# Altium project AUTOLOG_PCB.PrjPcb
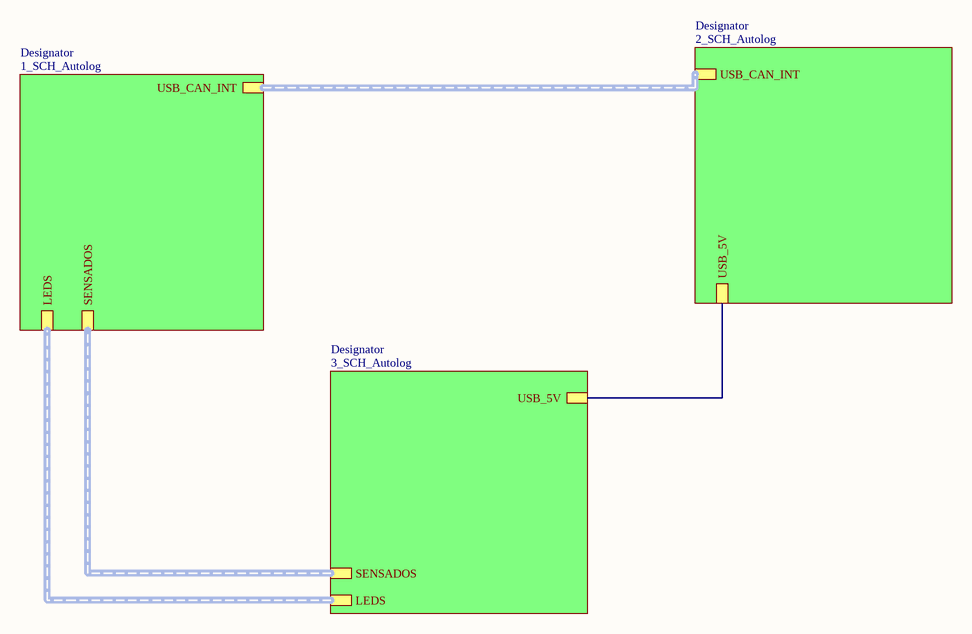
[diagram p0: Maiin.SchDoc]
4 sheets, 80 parts. Net scope: hierarchical (ports join the sheet entries above them; power ports are global).
Board file: PCB_Autolog.PcbDoc
Sheets:
  Maiin.SchDoc
    Designator = 1_SCH_Autolog.SchDoc
    Designator = 2_SCH_Autolog.SchDoc
    Designator = 3_SCH_Autolog.SchDoc

## Sheet Maiin.SchDoc: PROYECTO FINAL - AutoLog
size A4; Author: Nathalia Mora; Revision: V1R1; SheetNumber: 1; SheetTotal: 4; Name:: Marlyn Nathalia Mora Riascos

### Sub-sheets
Designator = 1_SCH_Autolog: LEDS (harness LEDS_HARNEERS), SENSADOS (harness SENSADO HARNEERS), USB_CAN_INT (harness USB_CAN_INT_HARNEERS)
Designator = 2_SCH_Autolog: USB_5V, USB_CAN_INT (harness USB_CAN_INT_HARNEERS)
Designator = 3_SCH_Autolog: LEDS (harness LEDS_HARNEERS), SENSADOS (harness SENSADO HARNEERS), USB_5V

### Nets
VBUSS: sheet Designator/USB_5V, sheet Designator/USB_5V

## Sheet 1_SCH_Autolog.SchDoc: PROYECTO FINAL - AutoLog
size A4; Revision: V1R1; SheetNumber: 2; SheetTotal: 4
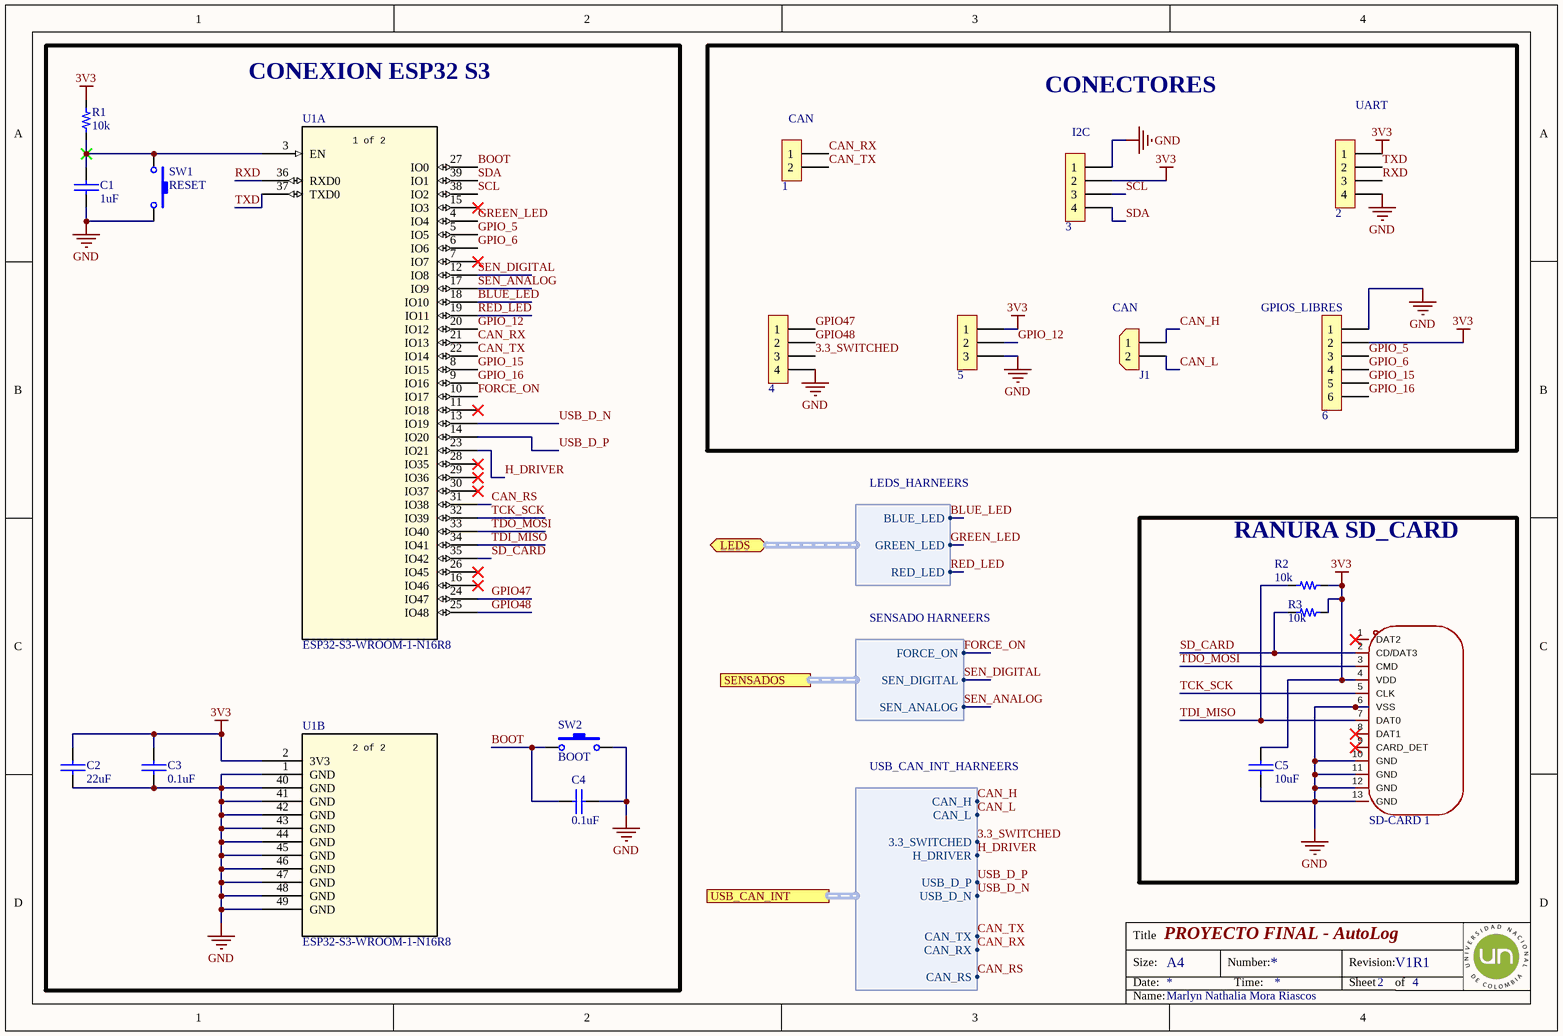
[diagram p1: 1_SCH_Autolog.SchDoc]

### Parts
1  2x1  [H_2x1_TH_100mil]  (value not drawn)  (no BOM)
2  4x1  [H_4x1_TH_2.54mm]  (value not drawn)  (no BOM)
3  4x1  [H_4x1_TH_2.54mm]  (value not drawn)  (no BOM)
4  4x1  [H_4x1_TH_2.54mm]  (value not drawn)  (no BOM)
5  3x1  [H_3X1_TH_100mil]  (value not drawn)  (no BOM)
6  6x1  [H_6x1_TH_100mil]  (value not drawn)  (no BOM)
C1  value 1uF  [0603_cap]  (hidden comment: 1uF 50V)
C2  value 22uF  [0805_cap]  (hidden comment: 22uF 16V)
C3  value 0.1uF  [0603_cap]  (hidden comment: 0.1uF 50V)
C4  value 0.1uF  [0603_cap]  (hidden comment: 0.1uF 50V)
C5  value 10uF  [0603_cap]  (hidden comment: 10uF 10V)
J1  CAN  [CON_2x1_TH_5MM]
R1  value 10k  [0603_res]  (hidden comment: 10k 1/10W)
R2  value 10k  [0603_res]  (hidden comment: 10k 1/10W)
R3  value 10k  [0603_res]  (hidden comment: 10k 1/10W)
SD-CARD_1  Micro_SD_socket  [MICROSD CARD SMD]  (value not drawn)
SW1  RESET  [Sw_PUSH_4.5x4.5x5mm]
SW2  BOOT  [Sw_PUSH_4.5x4.5x5mm]
U1  ESP32-S3-WROOM-1-N16R8  [ESP32S3WROOM1N8R2]  (parts A,B of 2)

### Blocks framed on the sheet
CONEXION ESP32 S3: C1-C4 R1 SW1 SW2 U1
CONECTORES: 1-6 J1
RANURA SD_CARD: C5 R2 R3 SD-CARD_1

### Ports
LEDS (bidir, harness LEDS_HARNEERS, see Maiin[2B], 3_SCH_Autolog[4C]), SENSADOS (harness SENSADO HARNEERS, see Maiin[2B], 3_SCH_Autolog[3A]), USB_CAN_INT (harness USB_CAN_INT_HARNEERS, see Maiin[2A], 2_SCH_Autolog[1D])

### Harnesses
LEDS_HARNEERS: RED_LED, GREEN_LED, BLUE_LED
SENSADO HARNEERS: FORCE_ON, SEN_DIGITAL, SEN_ANALOG
USB_CAN_INT_HARNEERS: USB_D_P, USB_D_N, H_DRIVER, 3.3_SWITCHED, CAN_L, CAN_TX, CAN_RX, CAN_RS, CAN_H

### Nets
3V3: 2.1 3.2 5.1 6.2 C2.1 C3.1 C5.2 R1.2 R2.2 R3.2 SD-CARD_1.4(VDD) U1.2(3V3)
GND: 2.4 3.1 4.4 5.3 6.1 C1.2 C2.2 C3.2 C4.1 C5.1 SD-CARD_1.6(VSS) SD-CARD_1.10(GND) SD-CARD_1.11(GND) SD-CARD_1.12(GND) SD-CARD_1.13(GND) SW1.2 SW2.2 U1.1(GND) U1.40(GND) U1.41(GND) U1.42(GND) U1.43(GND) U1.44(GND) U1.45(GND) U1.46(GND) U1.47(GND) U1.48(GND) U1.49(GND)
3.3_SWITCHED: 4.3 ; port USB_CAN_INT.3.3_SWITCHED
BLUE_LED: U1.18(IO10) ; port LEDS.BLUE_LED
BOOT: C4.2 SW2.1 U1.27(IO0)
CAN_H: J1.1 ; port USB_CAN_INT.CAN_H
CAN_L: J1.2 ; port USB_CAN_INT.CAN_L
CAN_RS: U1.31(IO38) ; port USB_CAN_INT.CAN_RS
CAN_RX: 1.1 U1.21(IO13) ; port USB_CAN_INT.CAN_RX
CAN_TX: 1.2 U1.22(IO14) ; port USB_CAN_INT.CAN_TX
FORCE_ON: U1.10(IO17) ; port SENSADOS.FORCE_ON
GPIO47: 4.1 U1.24(IO47)
GPIO48: 4.2 U1.25(IO48)
GPIO_5: 6.3 U1.5(IO5)
GPIO_6: 6.4 U1.6(IO6)
GPIO_12: 5.2 U1.20(IO12)
GPIO_15: 6.5 U1.8(IO15)
GPIO_16: 6.6 U1.9(IO16)
GREEN_LED: U1.4(IO4) ; port LEDS.GREEN_LED
H_DRIVER: U1.23(IO21) ; port USB_CAN_INT.H_DRIVER
RED_LED: U1.19(IO11) ; port LEDS.RED_LED
RXD: 2.3 U1.36(RXD0)
SCL: 3.3 U1.38(IO2)
SD_CARD: R3.1 SD-CARD_1.2(CD/DAT3) U1.35(IO42)
SDA: 3.4 U1.39(IO1)
SEN_ANALOG: U1.17(IO9) ; port SENSADOS.SEN_ANALOG
SEN_DIGITAL: U1.12(IO8) ; port SENSADOS.SEN_DIGITAL
TCK_SCK: SD-CARD_1.5(CLK) U1.32(IO39)
TDI_MISO: R2.1 SD-CARD_1.7(DAT0) U1.34(IO41)
TDO_MOSI: SD-CARD_1.3(CMD) U1.33(IO40)
TXD: 2.2 U1.37(TXD0)
USB_D_N: U1.13(IO19) ; port USB_CAN_INT.USB_D_N
USB_D_P: U1.14(IO20) ; port USB_CAN_INT.USB_D_P
NetC1_1: C1.1 R1.1 SW1.1 U1.3(EN)

Not connected (* = marked no-connect by the designer): SD-CARD_1 1(DAT2)* 8(DAT1)* 9(CARD_DET)*; U1 7(IO7)* 11(IO18)* 15(IO3)* 16(IO46)* 26(IO45)* 28(IO35)* 29(IO36)* 30(IO37)*

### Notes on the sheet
- (near 2) UART
- (near 1) CAN
- (near 3) I2C
- (near 6) GPIOS_LIBRES

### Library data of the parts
1 = H_Male_2x1_TH_100mil
2-4 = H_Male_4x1_TH_100mil
5 = H_Male_3x1_TH_100mil
6 = H_Male_6x1_TH_100mil
C1 = Cap_1uF_0603_50V: 50V 1uF X5R ±10% 0603 Multilayer Ceramic Capacitors MLCC - SMD/SMT ROHS; Manufacturer: Samsung Electro-Mechanics; Manufacturer Part Number: CL10A105KB8NNNC
C2 = Cap_22uF_0805_16V: 16V 22uF X5R ±20% 0805 Multilayer Ceramic Capacitors MLCC - SMD/SMT ROHS; Manufacturer: Chinocera; Manufacturer Part Number: HGC0805R5226M160NSLJ
C3 C4 = Cap_0.1uF_0603_50V: 50V 100nF Y5V -20%~+80% 0603 Multilayer Ceramic Capacitors MLCC - SMD/SMT ROHS; Manufacturer: Walsin Tech Corp; Manufacturer Part Number: 0603F104Z500CT
C5 = Cap_10uF_0603_10V: 10V 10uF X5R ±10% 0603 Multilayer Ceramic Capacitors MLCC - SMD/SMT ROHS; Manufacturer: CCTC; Manufacturer Part Number: TCC0603X5R106K100CT
J1 = Con_2x1_TH_5mm: 2POS 5MM; Manufacturer: JILN; Manufacturer Part Number: JL126-50002G01
R1-R3 = Res_10k_0603_1/10W: RES SMD 10k OHM 5% 1/10W 0603; Manufacturer: FOJAN; Manufacturer Part Number: FRC0603J103TS
SD-CARD_1 = Micro_SD_socket: CONN MICROSD CARD R/A SMD; Manufacturer: ATOM; Manufacturer Part Number: MR01A-01211
SW1 SW2 = Sw_PUSH_4.5x4.5x5.0xmm: SWITCH TACTILE SPST-NO 0.05A 12V; Manufacturer: BZCN; Manufacturer Part Number: TSC015A05026A
U1 = ESP32-S3-WROOM-1-N16R8  nnnnn: ESP32-S3 Wi-Fi & Bluetooth 5 MCU module, 16MB Flash, 8MB PSRAM.; Manufacturer: Espressif Systems; Suplier  Part Number: 5407-ESP32-S3-WROOM-1-N16R8TR-ND

## Sheet 2_SCH_Autolog.SchDoc: PROYECTO FINAL - AutoLog
size A4; SheetNumber: 3; SheetTotal: 4
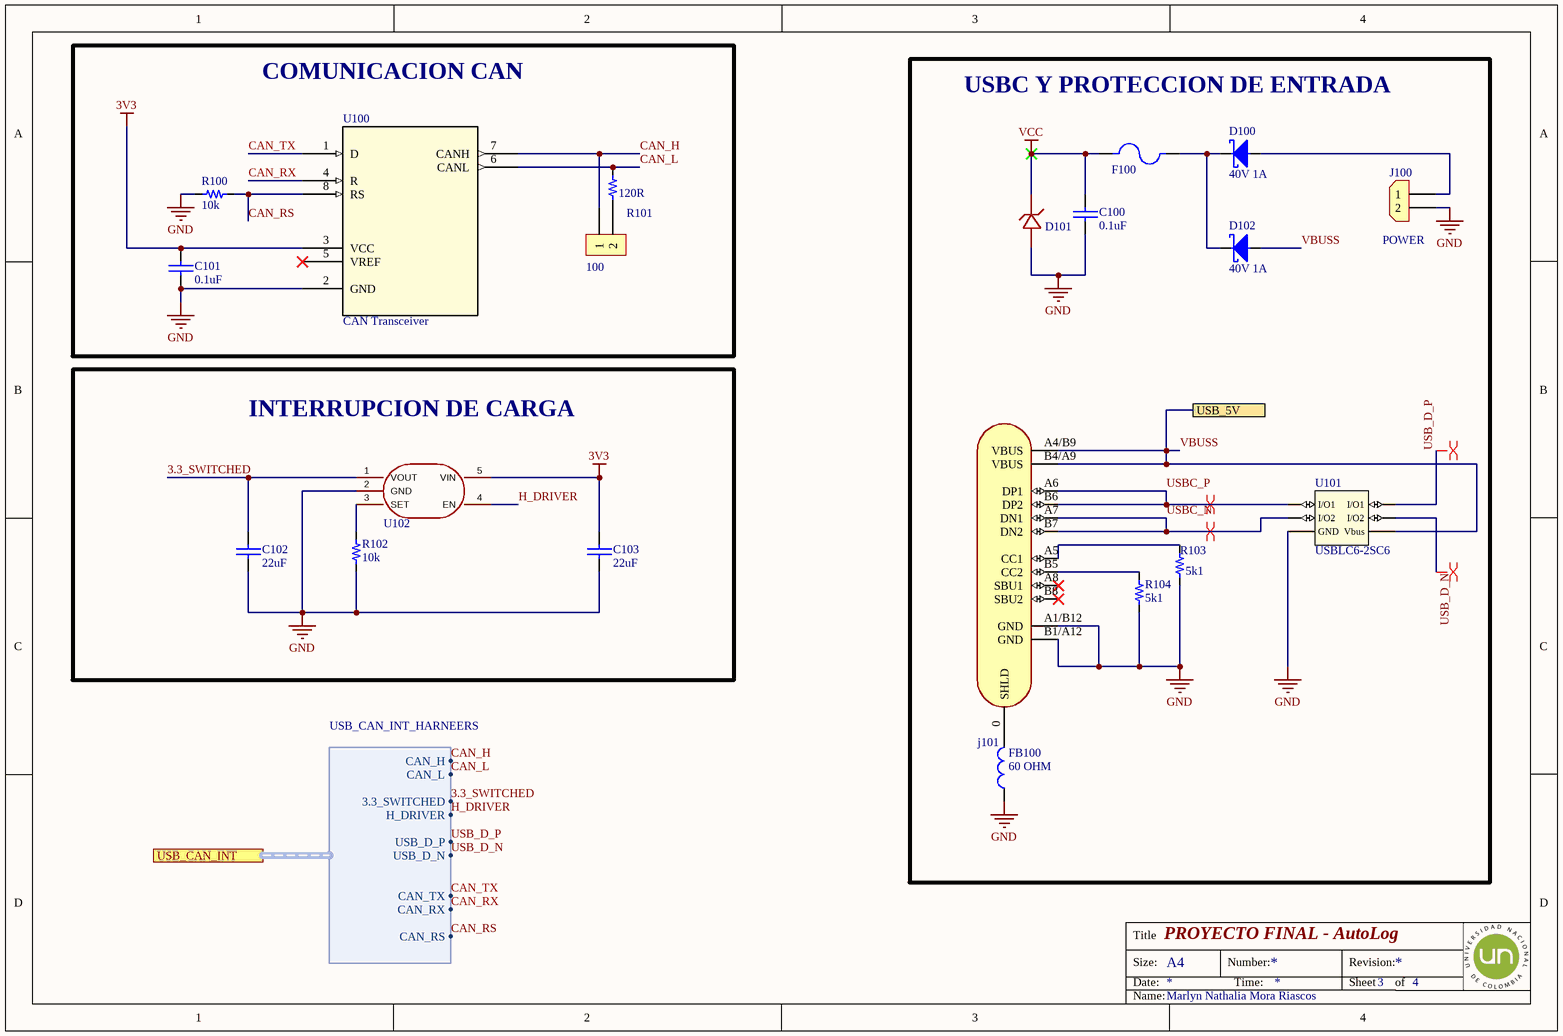
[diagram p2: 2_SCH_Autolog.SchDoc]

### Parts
100  2x1  [H_2x1_TH_100mil]  (value not drawn)  (no BOM)
C100  value 0.1uF  [0603_cap]  (hidden comment: 0.1uF 50V)
C101  value 0.1uF  [0603_cap]  (hidden comment: 0.1uF 50V)
C102  value 22uF  [0603_cap]  (hidden comment: 22uF 10V)
C103  value 22uF  [0603_cap]  (hidden comment: 22uF 10V)
D100  40V 1A  [SOD_123]
D101  TVS_DIODE_SMF30A  [TVS_DIODE_SMF30A]  (value not drawn)
D102  40V 1A  [SOD_123]
F100  PTC_MF-MSMF110/16-2  [FUSER_MF-MSMF110/16-2]  (value not drawn)
FB100  value 60 OHM  [0603_fb]  (hidden comment: 60OHM 2A)
J100  POWER  [CON_2x1_TH_5MM]
j101  USB C  [CON_USB_C_16P_RA]  (value not drawn)
R100  value 10k  [0603_res]  (hidden comment: 10k 1/10W)
R101  value 120R  [0603_res]  (hidden comment: 120R 1/10W)
R102  value 10k  [0603_res]  (hidden comment: 10k 1/10W)
R103  value 5k1  [0603_res]  (hidden comment: 5k1 1/10W)
R104  value 5k1  [0603_res]  (hidden comment: 5k1 1/10W)
U100  CAN Transceiver  [D8-M]
U101  USBLC6-2SC6  [SOT_23_6]
U102  MT9700  [SOT-23-5_L3.0-W1.7-P0.95-LS2.8-BR]  (value not drawn)

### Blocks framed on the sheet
COMUNICACION CAN: 100 C101 R100 R101 U100
USBC Y PROTECCION DE ENTRADA: C100 D100-D102 F100 FB100 J100 j101 R103 R104 U101
INTERRUPCION DE CARGA: C102 C103 R102 U102

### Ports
USB_5V (see Maiin[3B], 3_SCH_Autolog[3A]), USB_CAN_INT (harness USB_CAN_INT_HARNEERS, see Maiin[3A], 1_SCH_Autolog[2D])

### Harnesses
USB_CAN_INT_HARNEERS: USB_D_P, USB_D_N, H_DRIVER, 3.3_SWITCHED, CAN_L, CAN_TX, CAN_RX, CAN_RS, CAN_H

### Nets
3V3: C101.2 C103.1 U100.3(VCC) U102.5(VIN)
GND: C100.1 C101.1 C102.2 C103.2 D101.2 FB100.1 J100.2 j101.A1/B12(GND) j101.B1/A12(GND) R100.1 R102.1 R103.1 R104.2 U100.2(GND) U101.2(GND) U102.2(GND)
VCC: C100.2 D101.1 F100.1
3.3_SWITCHED: C102.1 U102.1(VOUT) ; port USB_CAN_INT.3.3_SWITCHED
CAN_H: 100.1 U100.7(CANH) ; port USB_CAN_INT.CAN_H
CAN_L: R101.2 U100.6(CANL) ; port USB_CAN_INT.CAN_L
CAN_RS: R100.2 U100.8(RS) ; port USB_CAN_INT.CAN_RS
CAN_RX: U100.4(R) ; port USB_CAN_INT.CAN_RX
CAN_TX: U100.1(D) ; port USB_CAN_INT.CAN_TX
H_DRIVER: U102.4(EN) ; port USB_CAN_INT.H_DRIVER
USB_D_N: U101.4(I/O2) ; port USB_CAN_INT.USB_D_N
USB_D_P: U101.6(I/O1) ; port USB_CAN_INT.USB_D_P
USBC_N: j101.A7(DN1) j101.B7(DN2) U101.3(I/O2)
USBC_P: j101.A6(DP1) j101.B6(DP2) U101.1(I/O1)
VBUSS: D102.2 j101.A4/B9(VBUS) j101.B4/A9(VBUS) U101.5(Vbus) ; port USB_5V
Net100_2: 100.2 R101.1
NetD100_1: D100.1 D102.1 F100.2
NetD100_2: D100.2 J100.1
NetFB100_2: FB100.2 j101.0(SHLD)
Netj101_A5: j101.A5(CC1) R103.2
Netj101_B5: j101.B5(CC2) R104.1
NetR102_2: R102.2 U102.3(SET)

Not connected (* = marked no-connect by the designer): j101 A8(SBU1)* B8(SBU2)*; U100 5(VREF)*

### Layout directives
differential pair: USB_D_N, USB_D_P, USBC_N, USBC_P

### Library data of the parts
100 = H_Male_2x1_TH_100mil
C100 C101 = Cap_0.1uF_0603_50V: as C3 on sheet 1_SCH_Autolog
C102 C103 = Cap_22uF_0603_10V: 10V 22uF X5R ±20% 0603 Multilayer Ceramic Capacitors MLCC - SMD/SMT ROHS; Manufacturer: HRE; Manufacturer Part Number: CGA0603X5R226M100JT
D100 D102 = D_Schottky_40V_1A_SOD_123F: DIODE SCHOTTKY 40V 1A SOD123F; Manufacturer: Shanghai Prisemi Elec; Manufacturer Part Number: PSBD1DF40V1H
D101 = TVS_DIODE_SMF30A: TVS DIODE 30VWM 48.4VC SOD123F; Manufacturer: Diotec Semiconductor; Manufacturer Part Number: SMF30A
F100 = PTC_MF-MSMF110/16-2: Polymeric PTC Resettable Fuse 16V 1.1 A Ih Surface Mount 1812 (4532 Metric), Concave; Manufacturer: Bourns Inc.
FB100 = FB_60_0603_2A: 2A 1 100mΩ 60Ω@100MHz ±25% 0603 Ferrite Beads ROHS; Manufacturer: TAI-TECH; Manufacturer Part Number: HCB1608KF-600T20
J100 = Con_2x1_TH_5mm: as J1 on sheet 1_SCH_Autolog
j101 = CON_USB_TYPEC_16P: 3A USB 3.1 1 Surface Mount 16P Female -40℃~+85℃ Type-C SMD USB Connectors ROHS; Manufacturer: SHOU HAN; Manufacturer Part Number: TYPE-C-3.1-16PIN
R100 R102 = Res_10k_0603_1/10W: as R1 on sheet 1_SCH_Autolog
R101 = Res_120R_0603_1/10W: 100mW Thick Film Resistor 75V ±100ppm/℃ ±1% 120Ω 0603 Chip Resistor - Surface Mount ROHS; Manufacturer: FOJAN; Manufacturer Part Number: FRC0603F1200TS
R103 R104 = Res_5k1_0603: RES 5.1kΩ ±1% 100mW 0603; Manufacturer: YAGEO; Manufacturer Part Number: RC0603FR-0773K2L
U100 = SN65HVD230DR-CAN: Transceiver Half CANbus 8-SOIC; Manufacturer: Texas Instruments; Suplier  Part Number: 296-11654-2-ND
U101 = TVS_5.25V_2CH_SOT_23_6: TVS DIODE 5.25V 17V SOT23-6; Manufacturer: STMicroelectronics
U102 = MT9700: Switch de potencia con límite de corriente y control enable para corte en sleep de periféricos y MicroSD; Manufacturer: XI'AN Aerosemi Tech

## Sheet 3_SCH_Autolog.SchDoc: PROYECTO FINAL - AutoLog
size A4; Revision: V1R1; SheetNumber: 4; SheetTotal: 4
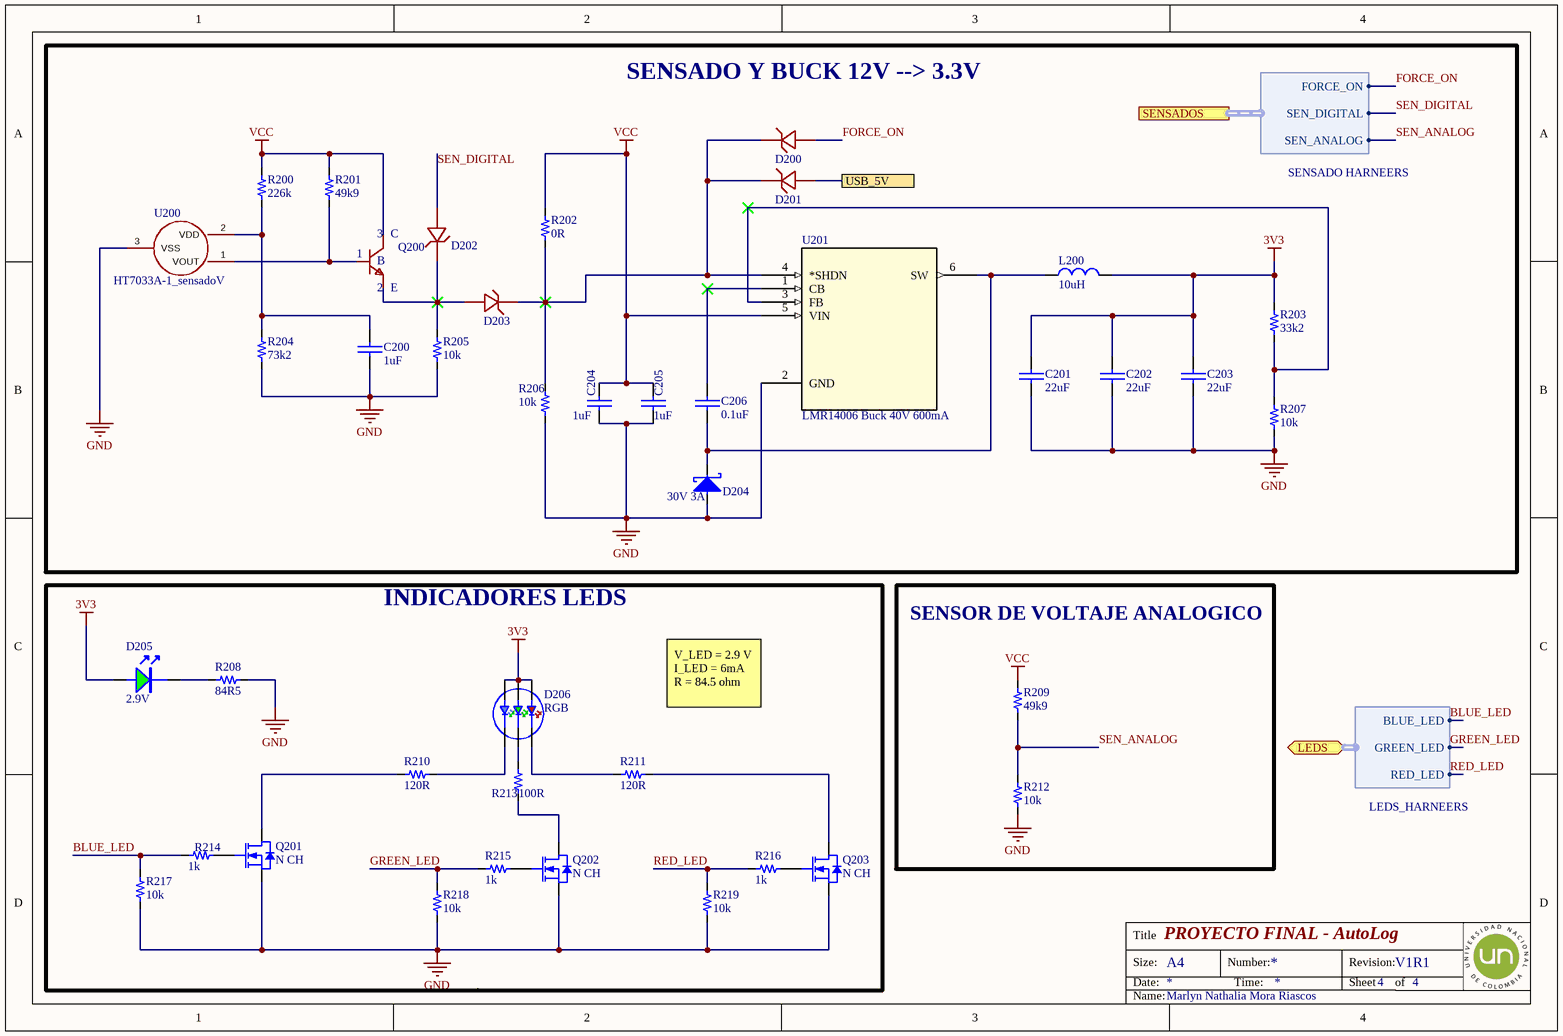
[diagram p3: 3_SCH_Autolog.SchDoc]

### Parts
C200  value 1uF  [0603_cap]  (hidden comment: 1uF 50V)
C201  value 22uF  [0603_cap]  (hidden comment: 22uF 10V)
C202  value 22uF  [0603_cap]  (hidden comment: 22uF 10V)
C203  value 22uF  [0603_cap]  (hidden comment: 22uF 10V)
C204  value 1uF  [0603_cap]  (hidden comment: 1uF 50V)
C205  value 1uF  [0603_cap]  (hidden comment: 1uF 50V)
C206  value 0.1uF  [0603_cap]  (hidden comment: 0.1uF 50V)
D200  1N4148WS  [SOD-323_1N4148]  (value not drawn)
D201  1N4148WS  [SOD-323_1N4148]  (value not drawn)
D202  1N4148WS  [SOD-323_1N4148]  (value not drawn)
D203  1N4148WS  [SOD-323_1N4148]  (value not drawn)
D204  30V 3A  [SMA]
D205  2.9V  [0805_LED]
D206  RGB  [RGB_NS_3.5X3.7]
L200  value 10uH  [Ind_5.8*5.2_NS]  (hidden comment: 10uH 1.42A)
Q200  SS8050  [SOT-23-3_TRANS NPN]  (value not drawn)
Q201  N CH  [SOT_23_3]
Q202  N CH  [SOT_23_3]
Q203  N CH  [SOT_23_3]
R200  value 226k  [0603_res]  (hidden comment: 226k 1/10W)
R201  value 49k9  [0603_res]  (hidden comment: 49k9 1/10W)
R202  value 0R  [0603_res]  (hidden comment: 0R 1/10W)
R203  value 33k2  [0603_res]  (hidden comment: 33k2 1/10W)
R204  value 73k2  [0603_res]  (hidden comment: 73k2 1/10W)
R205  value 10k  [0603_res]  (hidden comment: 10k 1/10W)
R206  value 10k  [0603_res]  (hidden comment: 10k 1/10W)
R207  value 10k  [0603_res]  (hidden comment: 10k 1/10W)
R208  value 84R5  [0603_res]  (hidden comment: 84R5 1/10W)
R209  value 49k9  [0603_res]  (hidden comment: 49k9 1/10W)
R210  value 120R  [0603_res]  (hidden comment: 120R 1/10W)
R211  value 120R  [0603_res]  (hidden comment: 120R 1/10W)
R212  value 10k  [0603_res]  (hidden comment: 10k 1/10W)
R213  value 100R  [0603_res]  (hidden comment: 100R 1/10W)
R214  value 1k  [0603_res]  (hidden comment: 1k 1/10W)
R215  value 1k  [0603_res]  (hidden comment: 1k 1/10W)
R216  value 1k  [0603_res]  (hidden comment: 1k 1/10W)
R217  value 10k  [0603_res]  (hidden comment: 10k 1/10W)
R218  value 10k  [0603_res]  (hidden comment: 10k 1/10W)
R219  value 10k  [0603_res]  (hidden comment: 10k 1/10W)
U200  HT7033A-1_sensadoV  [SOT-89-3_L4.5-W2.5-P1.50-LS4.2-BR]
U201  LMR14006 Buck 40V 600mA  [DDC6_TEX-M]

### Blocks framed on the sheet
SENSADO Y BUCK 12V --> 3.3V: C200-C206 D200-D204 L200 Q200 R200-R207 U200 U201
INDICADORES LEDS: D205 D206 Q201-Q203 R208 R210 R211 R213-R219
SENSOR DE VOLTAJE ANALOGICO: R209 R212

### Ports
LEDS (bidir, harness LEDS_HARNEERS, see Maiin[2C], 1_SCH_Autolog[2C]), SENSADOS (harness SENSADO HARNEERS, see Maiin[2C], 1_SCH_Autolog[2C]), USB_5V (see Maiin[3C], 2_SCH_Autolog[4B])

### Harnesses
LEDS_HARNEERS: RED_LED, GREEN_LED, BLUE_LED
SENSADO HARNEERS: FORCE_ON, SEN_DIGITAL, SEN_ANALOG

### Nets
3V3: C201.1 C202.1 C203.1 D205.1(A) D206.4 D206.5 D206.6 L200.2 R203.2
GND: C200.2 C201.2 C202.2 C203.2 C204.2 C205.2 D204.2 Q201.2(S) Q202.2(S) Q203.2(S) R204.1 R205.1 R206.1 R207.1 R208.2 R212.1 R217.2 R218.1 R219.1 U200.3(VSS) U201.2(GND)
VCC: C204.1 C205.1 Q200.3(C) R200.2 R201.1 R202.2 R209.2 U201.5(VIN)
BLUE_LED: R214.1 R217.1 ; port LEDS.BLUE_LED
FORCE_ON: D200.2 ; port SENSADOS.FORCE_ON
GREEN_LED: R215.1 R218.2 ; port LEDS.GREEN_LED
RED_LED: R216.1 R219.2 ; port LEDS.RED_LED
SEN_ANALOG: R209.1 R212.2 ; port SENSADOS.SEN_ANALOG
SEN_DIGITAL: D202.2 ; port SENSADOS.SEN_DIGITAL
VBUSS: D201.2 ; port USB_5V
NetC200_1: C200.1 R200.1 R204.2 U200.2(VDD)
NetC206_1: C206.1 U201.1(CB)
NetC206_2: C206.2 D204.1 L200.1 U201.6(SW)
NetD200_1: D200.1 D201.1 D203.1 R202.1 R206.2 U201.4(*SHDN)
NetD202_1: D202.1 D203.2 Q200.2(E) R205.2
NetD205_2: D205.2 R208.1
NetD206_1: D206.1 R210.1
NetD206_2: D206.2 R213.1
NetD206_3: D206.3 R211.1
NetQ200_1: Q200.1(B) R201.2 U200.1(VOUT)
NetQ201_1: Q201.1(G) R214.2
NetQ201_3: Q201.3(D) R210.2
NetQ202_1: Q202.1(G) R215.2
NetQ202_3: Q202.3(D) R213.2
NetQ203_1: Q203.1(G) R216.2
NetQ203_3: Q203.3(D) R211.2
NetR203_1: R203.1 R207.2 U201.3(FB)

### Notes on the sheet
- V_LED = 2.9 V
  I_LED = 6mA
  R = 84.5 ohm

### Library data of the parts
C200 C204 C205 = Cap_1uF_0603_50V: as C1 on sheet 1_SCH_Autolog
C201-C203 = Cap_22uF_0603_10V: as C102 on sheet 2_SCH_Autolog
C206 = Cap_0.1uF_0603_50V: as C3 on sheet 1_SCH_Autolog
D200-D203 = 1N4148WS_DIODE: DIODE GP 100V 150mA SOD-323; Manufacturer: JSCJ
D204 = D_Schottky_40V_3A_SMA: 40V Independent 3A 550mV@3A SMA Schottky Diodes ROHS; Manufacturer: TDSEMIC; Manufacturer Part Number: SS34-TD
D205 = LED_0805_Green: LED GREEN CLEAR 0805 SMD; Manufacturer: XINGLIGHT; Manufacturer Part Number: XL-2012UGC
D206 = LED_RGB_3535_SMD: -30℃~+85℃ RGB 110° 3535(mm) Light Emitting Diodes (LED) ROHS; Manufacturer: Foshan NationStar Optoelectronics; Manufacturer Part Number: RS-3535MWAM
L200 = Inductor_10uH_1.42A_5.8*5.2mm: 1.42A 10uH ±10% 87.9mΩ SMD,5.8x5.2mm Inductors (SMD) ROHS; Manufacturer: SHOU HAN; Manufacturer Part Number: CY54-10UH
Q200 = TRANS_NPN_SS8050_SOT23: SS8050 Transistor BJT NPN 40V 1.5A; Manufacturer: JSCJ; Manufacturer Part Number: SS8050(RANGE:200-350)
Q201-Q203 = Q_NFET_20V_3.2A_SOT23: MOSFET N-CH 20V SOT23; Manufacturer: Doeshare; Manufacturer Part Number: DN2302S
R200 = Res_226k_0603_1/10W: 100mW Thick Film Resistors 75V ±100ppm/℃ ±1% 226kΩ 0603 Chip Resistor - Surface Mount ROHS; Manufacturer: YAGEO; Manufacturer Part Number: RC0603FR-07226KL
R201 R209 = Res_49k9_0603_1/10W: 100mW Thick Film Resistor 75V ±100ppm/℃ ±1% 49.9kΩ 0603 Chip Resistor - Surface Mount ROHS; Manufacturer: YAGEO; Manufacturer Part Number: RC0603FR-0749K9L
R202 = Res_0R_0603_1/10W: RES SMD 0R OHM 5% 1/10W 0603; Manufacturer: FOJAN; Manufacturer Part Number: FRC0603P000 TS
R203 = Res_33k2_0603_1/10W: 100mW Thick Film Resistor 75V ±100ppm/℃ ±1% 33.2kΩ 0603 Chip Resistor - Surface Mount ROHS; Manufacturer: YAGEO; Manufacturer Part Number: RC0603FR-0733K2L
R204 = Res_73k2_0603_1/10W: 100mW Thick Film Resistor 75V ±100ppm/℃ ±1% 73.2kΩ 0603 Chip Resistor - Surface Mount ROHS; Manufacturer: YAGEO; Manufacturer Part Number: RC0603FR-0773K2L
R205-R207 R212 R217-R219 = Res_10k_0603_1/10W: as R1 on sheet 1_SCH_Autolog
R208 = Res_84R5_0603_1/10W: 100mW Thick Film Resistor 50V ±100ppm/℃ ±1% 84.5Ω 0603 Chip Resistor - Surface Mount ROHS; Manufacturer: LIZ Elec; Manufacturer Part Number: CR0603FA84R5G
R210 R211 = Res_120R_0603_1/10W: as R101 on sheet 2_SCH_Autolog
R213 = Res_100R_0603_1/10W: RES SMD 100R OHM 5% 1/10W 0603; Manufacturer: FOJAN; Manufacturer Part Number: FRC0603J101 TS
R214-R216 = Res_1k_0603_1/10W: RES SMD 1k OHM 5% 1/10W 0603; Manufacturer: FOJAN; Manufacturer Part Number: FRC0603J102 TS
U200 = HOLTEK HT7033A-1_sensadoV: Detector de tensión con umbral de 3.3V; Manufacturer: HOLTEK; Suplier  Part Number: C73715
U201 = LMR14006XDDCR: IC REG BUCK ADJ 600MA SOT23; Manufacturer: Texas Instruments; Suplier  Part Number: 296-44318-2-ND

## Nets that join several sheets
3V3: 1_SCH_Autolog (12 pins), 2_SCH_Autolog (C101.2 C103.1 U100.3 U102.5), 3_SCH_Autolog (9 pins)
GND: 1_SCH_Autolog (28 pins), 2_SCH_Autolog (16 pins), 3_SCH_Autolog (21 pins)
VCC: 2_SCH_Autolog (C100.2 D101.1 F100.1), 3_SCH_Autolog (8 pins)
3.3_SWITCHED: 1_SCH_Autolog (4.3), 2_SCH_Autolog (C102.1 U102.1)
BLUE_LED: 1_SCH_Autolog (U1.18), 3_SCH_Autolog (R214.1 R217.1)
CAN_H: 1_SCH_Autolog (J1.1), 2_SCH_Autolog (100.1 U100.7)
CAN_L: 1_SCH_Autolog (J1.2), 2_SCH_Autolog (R101.2 U100.6)
CAN_RS: 1_SCH_Autolog (U1.31), 2_SCH_Autolog (R100.2 U100.8)
CAN_RX: 1_SCH_Autolog (1.1 U1.21), 2_SCH_Autolog (U100.4)
CAN_TX: 1_SCH_Autolog (1.2 U1.22), 2_SCH_Autolog (U100.1)
FORCE_ON: 1_SCH_Autolog (U1.10), 3_SCH_Autolog (D200.2)
GREEN_LED: 1_SCH_Autolog (U1.4), 3_SCH_Autolog (R215.1 R218.2)
H_DRIVER: 1_SCH_Autolog (U1.23), 2_SCH_Autolog (U102.4)
RED_LED: 1_SCH_Autolog (U1.19), 3_SCH_Autolog (R216.1 R219.2)
SEN_ANALOG: 1_SCH_Autolog (U1.17), 3_SCH_Autolog (R209.1 R212.2)
SEN_DIGITAL: 1_SCH_Autolog (U1.12), 3_SCH_Autolog (D202.2)
USB_D_N: 1_SCH_Autolog (U1.13), 2_SCH_Autolog (U101.4)
USB_D_P: 1_SCH_Autolog (U1.14), 2_SCH_Autolog (U101.6)
VBUSS: 2_SCH_Autolog (D102.2 j101.A4/B9 j101.B4/A9 U101.5), 3_SCH_Autolog (D201.2)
